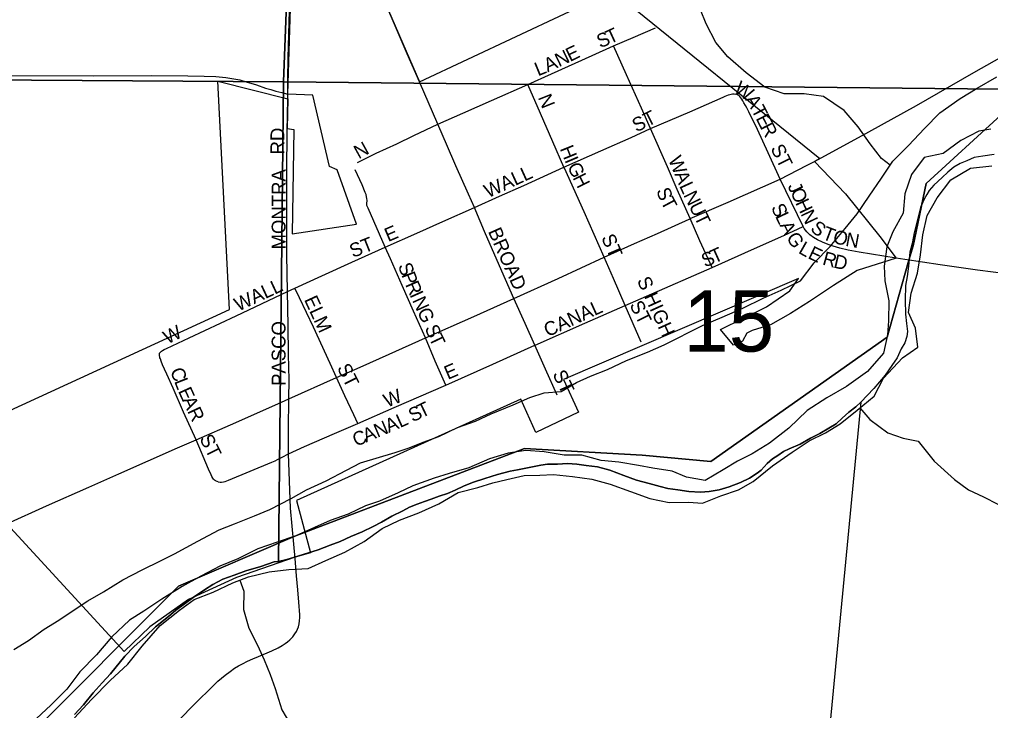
# Model space of a CAD drawing. Extents: x 0 to 1391, y -24 to 440.
# Drawn here: x 599.74 to 613.03, y 326.06 to 335.51 of the extents above; entities that cross this region are included whole.
import ezdxf

# ---------------------------------------------------------------- set-up
doc = ezdxf.new("R2010")
doc.units = 0
for name, color, linetype in [('GM_X_City_Street', 7, 'Continuous'), ('GM_X_City_Street_Text', 7, 'Continuous'), ('GM_X_Corporation', 7, 'Continuous'), ('GM_X_County_Road', 7, 'Continuous'), ('GM_X_Major_River', 7, 'Continuous'), ('GM_X_Minor_River', 7, 'Continuous'), ('GM_X_Section', 7, 'Continuous'), ('GM_X_Section_Text', 7, 'Continuous'), ('GM_X_State_Route', 7, 'Continuous'), ('GM_X_Township', 7, 'Continuous'), ('GM_X_Township_Road', 7, 'Continuous')]:
    doc.layers.add(name, color=color, linetype=linetype)

msp = doc.modelspace()

# ---------------------------------------------------------------- linework, layer by layer
at = {"layer": 'GM_X_City_Street'}
for points in [[(607.874, 335.147), (608.14, 335.263), (608.447, 335.393)], [(606.7, 334.62), (607.024, 334.766), (607.578, 335.015), (607.874, 335.147)], [(608.378, 334.016), (608.253, 334.296), (608.052, 334.75), (607.874, 335.147)], [(605.469, 334.077), (605.218, 334.654)], [(605.469, 334.077), (605.809, 334.228), (606.202, 334.4), (606.7, 334.62)], [(607.193, 333.49), (607.041, 333.835), (606.872, 334.223), (606.7, 334.62)], [(608.378, 334.016), (608.916, 334.247), (609.372, 334.448), (609.402, 334.46), (609.424, 334.469), (609.445, 334.477), (609.466, 334.483), (609.483, 334.488), (609.502, 334.491), (609.522, 334.492), (609.54, 334.488)], [(610.153, 333.326), (609.99, 333.683), (609.841, 334.002), (609.723, 334.246), (609.696, 334.299), (609.678, 334.33), (609.656, 334.37), (609.642, 334.396), (609.628, 334.419), (609.615, 334.437), (609.602, 334.455), (609.59, 334.466), (609.577, 334.474), (609.559, 334.483), (609.54, 334.488)], [(604.368, 333.554), (604.625, 333.679), (604.905, 333.809), (605.14, 333.921), (605.469, 334.077)], [(605.968, 332.939), (605.887, 333.121), (605.716, 333.506), (605.588, 333.802), (605.483, 334.045), (605.469, 334.077)], [(607.193, 333.49), (607.699, 333.714), (608.112, 333.895), (608.378, 334.016)], [(608.922, 332.785), (608.745, 333.183), (608.611, 333.491), (608.378, 334.016)], [(603.401, 332.556), (603.4, 332.631), (603.402, 333.047), (603.399, 333.426), (603.406, 333.978)], [(605.968, 332.939), (606.314, 333.09), (606.647, 333.24), (607.193, 333.49)], [(607.746, 332.259), (607.471, 332.88), (607.201, 333.473), (607.193, 333.49)], [(604.747, 332.395), (604.513, 332.927), (604.506, 332.944), (604.501, 332.955), (604.497, 332.965), (604.495, 332.974), (604.495, 332.987), (604.496, 332.996), (604.498, 333.008), (604.499, 333.019), (604.5, 333.034), (604.498, 333.06), (604.493, 333.084), (604.485, 333.114), (604.474, 333.143), (604.43, 333.246), (604.337, 333.451)], [(610.468, 332.675), (610.153, 333.326)], [(604.747, 332.395), (605.179, 332.585), (605.534, 332.744), (605.968, 332.939)], [(606.508, 331.692), (606.282, 332.211), (606.105, 332.608), (605.988, 332.892), (605.968, 332.939)], [(609.221, 332.117), (609.055, 332.481), (608.922, 332.785)], [(603.412, 331.787), (603.402, 332.292), (603.401, 332.556)], [(609.221, 332.117), (609.803, 332.377), (610.201, 332.553), (610.468, 332.675)], [(611.74, 332.246), (611.234, 332.326), (611.083, 332.355), (610.971, 332.379), (610.878, 332.406), (610.811, 332.431), (610.734, 332.463), (610.665, 332.495), (610.607, 332.529), (610.559, 332.564), (610.516, 332.605), (610.48, 332.651), (610.468, 332.675)], [(603.51, 331.832), (603.881, 332.004), (604.29, 332.189), (604.747, 332.395)], [(605.298, 331.154), (605.136, 331.518), (604.979, 331.87), (604.818, 332.234), (604.747, 332.395)], [(608.031, 331.598), (607.872, 331.967), (607.746, 332.259)], [(608.031, 331.598), (608.325, 331.723), (609.221, 332.117)], [(601.66, 330.943), (601.667, 330.954), (601.676, 330.965), (601.687, 330.973), (601.699, 330.98), (601.724, 330.993), (601.755, 331.009), (602.063, 331.156), (602.706, 331.454), (603.412, 331.787)], [(603.412, 331.787), (603.51, 331.832)], [(603.428, 330.32), (603.431, 330.582), (603.426, 330.927), (603.419, 331.322), (603.412, 331.787)], [(604.083, 330.613), (603.995, 330.803), (603.765, 331.3), (603.575, 331.7), (603.51, 331.832)], [(606.797, 331.053), (606.663, 331.352), (606.508, 331.692)], [(606.797, 331.053), (606.8, 331.055), (607.481, 331.357), (608.031, 331.598)], [(608.249, 331.097), (608.031, 331.598)], [(605.575, 330.507), (605.431, 330.835), (605.298, 331.154)], [(605.575, 330.507), (606.222, 330.793), (606.797, 331.053)], [(607.101, 330.372), (606.942, 330.724), (606.797, 331.053)], [(602.161, 329.76), (601.988, 330.138), (601.845, 330.465), (601.758, 330.656), (601.728, 330.724), (601.701, 330.786), (601.683, 330.834), (601.67, 330.868), (601.665, 330.88), (601.661, 330.893), (601.658, 330.905), (601.657, 330.917), (601.657, 330.931), (601.66, 330.943)], [(604.371, 329.985), (604.317, 330.1), (604.196, 330.361), (604.083, 330.613)], [(604.371, 329.985), (604.869, 330.204), (605.575, 330.507)], [(603.422, 329.568), (603.422, 329.911), (603.428, 330.32)], [(603.422, 329.568), (603.642, 329.668), (604.055, 329.847), (604.371, 329.985)], [(602.463, 329.185), (602.447, 329.189), (602.424, 329.198), (602.409, 329.21), (602.396, 329.223), (602.387, 329.237), (602.376, 329.258), (602.365, 329.281), (602.331, 329.36), (602.161, 329.76)], [(602.463, 329.185), (602.487, 329.182), (602.507, 329.182), (602.535, 329.187), (602.556, 329.192), (602.58, 329.2), (602.602, 329.209), (603.198, 329.455), (603.241, 329.474), (603.275, 329.491), (603.31, 329.507), (603.336, 329.522), (603.422, 329.568)], [(603.514, 328.138), (603.497, 328.332), (603.453, 328.827), (603.422, 329.568)]]:
    msp.add_lwpolyline(points, dxfattribs=at)
at = {"layer": 'GM_X_Corporation'}
for points in [[(598.982, 329.873), (602.617, 331.542), (602.457, 334.665), (603.413, 334.422), (603.406, 334.018), (603.495, 334.003), (603.472, 332.576), (604.355, 332.708), (604.092, 333.454), (603.987, 333.499), (603.758, 334.475), (603.414, 334.487), (603.529, 338.162)], [(604.656, 335.952), (605.218, 334.654), (607.865, 335.9), (610.698, 333.607), (610.621, 333.565), (611.049, 333.125), (611.515, 332.54), (611.74, 332.246), (611.209, 332.074), (610.882, 331.872), (610.555, 331.653), (610.294, 331.489), (610.019, 331.333), (609.772, 331.253), (609.699, 331.218), (609.637, 331.107), (609.515, 331.055), (609.336, 331.269), (609.964, 331.58), (610.287, 331.799), (610.405, 331.966), (607.189, 330.583), (607.391, 330.136), (606.809, 329.861), (606.602, 330.317), (603.535, 328.928), (603.723, 328.216), (603.513, 328.156), (602.712, 327.878), (602.056, 327.578), (601.527, 327.202), (601.176, 326.864), (599.57, 328.613)]]:
    msp.add_lwpolyline(points, dxfattribs=at)
at = {"layer": 'GM_X_County_Road'}
for points in [[(603.417, 334.687), (603.421, 334.983), (603.439, 335.628), (603.456, 336.049), (603.472, 336.506), (603.489, 336.95), (603.495, 337.173), (603.502, 337.384), (603.514, 337.77), (603.529, 338.162)], [(603.414, 334.487), (603.417, 334.687)], [(603.406, 333.978), (603.413, 334.422), (603.414, 334.487)], [(613.496, 331.997), (612.855, 332.081), (612.345, 332.153), (611.857, 332.226), (611.74, 332.246)], [(601.813, 325.809), (602.076, 326.087), (602.459, 326.459), (602.555, 326.54), (602.625, 326.593), (602.687, 326.635), (602.741, 326.667), (602.795, 326.695), (602.863, 326.732), (602.938, 326.765), (603.012, 326.798), (603.195, 326.874), (603.283, 326.916), (603.336, 326.946), (603.379, 326.975), (603.412, 326.998), (603.443, 327.023), (603.483, 327.064), (603.512, 327.107), (603.534, 327.138), (603.549, 327.168), (603.56, 327.204), (603.57, 327.243), (603.576, 327.286), (603.58, 327.329), (603.58, 327.367), (603.566, 327.538), (603.552, 327.707), (603.535, 327.898), (603.514, 328.138)]]:
    msp.add_lwpolyline(points, dxfattribs=at)
at = {"layer": 'GM_X_Major_River'}
for points in [[(613.034, 334.007), (612.871, 333.982), (612.625, 333.852), (612.384, 333.675)], [(612.384, 333.675), (612.124, 333.621), (611.951, 333.389), (611.86, 333.125), (611.838, 332.859), (611.695, 332.604), (611.614, 332.4), (611.577, 332.135), (611.587, 331.936), (611.641, 331.661), (611.634, 331.387), (611.621, 331.197), (611.569, 330.947), (611.35, 330.694), (611.063, 330.488), (610.793, 330.335), (610.522, 330.159), (610.272, 329.921), (610.009, 329.715), (609.769, 329.569), (609.569, 329.467), (609.375, 329.35), (609.128, 329.204), (608.871, 329.249), (608.675, 329.33), (608.41, 329.374), (608.213, 329.41), (607.947, 329.455), (607.704, 329.476), (607.44, 329.551), (607.196, 329.55), (606.924, 329.595), (606.673, 329.616), (606.429, 329.577), (606.175, 329.499), (605.891, 329.377), (605.623, 329.3), (605.416, 329.237), (605.124, 329.13), (604.923, 329.036), (604.669, 328.921), (604.478, 328.857), (604.239, 328.741), (603.993, 328.656), (603.778, 328.562), (603.524, 328.447), (603.27, 328.362), (603.002, 328.27), (602.732, 328.132), (602.486, 328.031), (602.224, 327.893), (601.969, 327.755), (601.691, 327.579), (601.443, 327.418), (601.25, 327.294), (601.008, 327.064), (600.796, 326.818), (600.57, 326.587), (600.389, 326.348), (600.17, 326.133), (599.913, 325.888)], [(600.493, 325.957), (600.728, 326.21), (600.985, 326.47), (601.227, 326.693), (601.423, 326.939), (601.666, 327.222), (601.93, 327.429), (602.132, 327.576), (602.393, 327.676), (602.663, 327.806), (602.878, 327.885), (603.161, 327.954), (603.428, 327.985), (603.695, 328.001), (603.934, 328.109), (604.195, 328.224), (604.458, 328.37), (604.706, 328.547), (604.944, 328.662), (605.206, 328.762), (605.483, 328.885), (605.745, 329.038), (606.013, 329.107), (606.22, 329.171), (606.412, 329.219), (606.649, 329.274), (606.862, 329.276), (607.053, 329.287), (607.311, 329.257), (607.576, 329.22), (607.826, 329.153), (608.105, 329.055), (608.369, 328.957), (608.634, 328.904), (608.9, 328.905), (609.09, 328.893), (609.343, 328.993), (609.582, 329.078), (609.782, 329.188), (610.046, 329.402), (610.317, 329.593), (610.55, 329.747), (610.773, 329.856), (610.974, 329.98), (611.207, 330.164), (611.44, 330.356), (611.568, 330.604), (611.826, 330.88), (612.035, 331.027), (612.004, 331.286), (611.911, 331.502), (611.948, 331.767), (612.031, 332.039), (612.075, 332.29), (612.105, 332.563), (612.165, 332.828), (612.3, 333.068), (612.489, 333.314), (612.76, 333.475), (613.05, 333.506)]]:
    msp.add_lwpolyline(points, dxfattribs=at)
at = {"layer": 'GM_X_Minor_River'}
for points in [[(611.659, 333.514), (611.538, 333.605), (611.383, 333.807), (611.222, 334.039), (611.029, 334.265), (610.745, 334.455), (610.48, 334.492), (610.206, 334.491), (609.942, 334.581), (609.688, 334.778), (609.435, 334.998), (609.272, 335.192), (609.142, 335.447), (609.063, 335.639)], [(606.921, 330.402), (607.158, 330.419), (607.366, 330.543), (607.559, 330.629), (607.789, 330.723), (608.051, 330.845), (608.336, 330.96), (608.566, 331.061), (609.09, 331.322), (609.36, 331.437), (609.644, 331.559), (609.922, 331.697), (610.168, 331.805), (610.43, 331.935), (610.619, 332.182), (610.838, 332.404), (611.042, 332.651), (611.207, 332.852), (611.373, 333.091), (611.539, 333.338), (611.697, 333.57), (611.908, 333.786), (612.127, 334.016), (612.337, 334.232), (612.616, 334.43), (612.848, 334.569), (613.119, 334.722)], [(599.664, 326.892), (599.865, 327.016), (600.082, 327.171), (600.283, 327.295), (600.477, 327.427), (600.678, 327.559), (600.894, 327.683), (601.157, 327.844), (601.419, 327.982), (601.673, 328.105), (601.866, 328.199), (602.182, 328.374), (602.475, 328.527), (602.683, 328.613), (602.96, 328.72), (603.167, 328.806), (603.46, 328.959), (603.669, 329.075), (603.938, 329.198), (604.216, 329.343), (604.409, 329.445), (604.884, 329.585), (605.076, 329.649), (605.268, 329.728), (605.483, 329.806), (605.737, 329.929), (605.983, 330.014), (606.199, 330.115), (606.499, 330.237), (606.729, 330.338), (606.921, 330.402)], [(611.244, 330.195), (611.379, 330.038), (611.625, 329.857), (611.837, 329.783), (612.041, 329.74), (612.262, 329.468), (612.538, 329.217), (612.732, 329.075), (612.935, 328.979), (613.13, 328.882)], [(602.757, 327.84), (602.812, 327.688), (602.806, 327.437), (602.883, 327.184), (602.999, 326.952), (603.093, 326.752), (603.171, 326.552), (603.243, 326.36), (603.334, 326.068), (603.451, 325.867)]]:
    msp.add_lwpolyline(points, dxfattribs=at)
at = {"layer": 'GM_X_Section'}
for points in [[(603.709, 343.811), (603.356, 334.656), (583.361, 334.79), (583.446, 343.811)], [(618.064, 334.507), (603.356, 334.656), (603.709, 343.811)], [(583.361, 334.79), (603.356, 334.656), (603.288, 328.097), (603.227, 328.091), (603.044, 328.026), (602.839, 327.969), (602.679, 327.911), (602.526, 327.853), (602.388, 327.779), (602.274, 327.706), (602.12, 327.602), (601.998, 327.514), (601.883, 327.432), (601.782, 327.343), (601.606, 327.202), (601.467, 327.068), (601.313, 326.935), (601.182, 326.801), (600.989, 326.561), (600.873, 326.435), (600.749, 326.3), (600.618, 326.136), (600.494, 326.002)], [(613.08, 333.661), (612.928, 333.641), (612.807, 333.621), (612.707, 333.577), (612.616, 333.541), (612.532, 333.489), (612.447, 333.422), (612.37, 333.348), (612.255, 333.244), (612.193, 333.169), (612.162, 333.117), (612.122, 333.049), (612.075, 332.937), (612.034, 332.771), (611.986, 332.59), (611.96, 332.446), (611.928, 332.325), (611.91, 332.136), (611.892, 331.993), (611.867, 331.872), (611.864, 331.668), (611.868, 331.478), (611.881, 331.349), (611.894, 331.243), (611.885, 331.175), (611.861, 331.084), (611.807, 331.002), (611.752, 330.882), (611.682, 330.777), (611.588, 330.642), (611.434, 330.463), (611.256, 330.277), (611.187, 330.21), (611.095, 330.136), (611.003, 330.054), (610.918, 329.98), (610.818, 329.921), (610.696, 329.847), (610.566, 329.781), (610.428, 329.7), (610.276, 329.635), (610.199, 329.598), (610.123, 329.547), (610.046, 329.502), (609.977, 329.436), (609.892, 329.346), (609.838, 329.302), (609.731, 329.235), (609.609, 329.177), (609.456, 329.119), (609.319, 329.076), (609.182, 329.055), (609.061, 329.042), (608.902, 329.053), (608.751, 329.078), (608.615, 329.096), (608.509, 329.12), (608.359, 329.161), (608.185, 329.209), (608.012, 329.273), (607.824, 329.344), (607.651, 329.392), (607.499, 329.41), (607.371, 329.428), (607.242, 329.437), (607.106, 329.425), (606.97, 329.427), (606.878, 329.413), (606.559, 329.351), (606.46, 329.33), (606.369, 329.309), (606.285, 329.287), (606.11, 329.23), (605.958, 329.179), (605.828, 329.129), (605.706, 329.07), (605.599, 329.027), (605.485, 328.991), (605.378, 328.947), (605.287, 328.918), (605.187, 328.882), (605.081, 328.839), (604.989, 328.787), (604.836, 328.714), (604.698, 328.633), (604.584, 328.575), (604.431, 328.501), (604.278, 328.436), (604.133, 328.37), (603.996, 328.32), (603.828, 328.254), (603.554, 328.168), (603.402, 328.125), (603.288, 328.097), (603.356, 334.656), (618.064, 334.507)], [(613.08, 333.661), (612.928, 333.641), (612.807, 333.621), (612.707, 333.577), (612.616, 333.541), (612.532, 333.489), (612.447, 333.422), (612.37, 333.348), (612.255, 333.244), (612.193, 333.169), (612.162, 333.117), (612.122, 333.049), (612.075, 332.937), (612.034, 332.771), (611.986, 332.59), (611.96, 332.446), (611.928, 332.325), (611.91, 332.136), (611.892, 331.993), (611.867, 331.872), (611.864, 331.668), (611.868, 331.478), (611.881, 331.349), (611.894, 331.243), (611.885, 331.175), (611.861, 331.084), (611.807, 331.002), (611.752, 330.882), (611.682, 330.777), (611.588, 330.642), (611.434, 330.463), (611.256, 330.277), (610.008, 317.239)], [(600.494, 326.002), (600.618, 326.136), (600.749, 326.3), (600.873, 326.435), (600.989, 326.561), (601.182, 326.801), (601.313, 326.935), (601.467, 327.068), (601.606, 327.202), (601.782, 327.343), (601.883, 327.432), (601.998, 327.514), (602.12, 327.602), (602.274, 327.706), (602.388, 327.779), (602.526, 327.853), (602.679, 327.911), (602.839, 327.969), (603.044, 328.026), (603.227, 328.091), (603.288, 328.097), (603.402, 328.125), (603.554, 328.168), (603.828, 328.254), (603.996, 328.32), (604.133, 328.37), (604.278, 328.436), (604.431, 328.501), (604.584, 328.575), (604.698, 328.633), (604.836, 328.714), (604.989, 328.787), (605.081, 328.839), (605.187, 328.882), (605.287, 328.918), (605.378, 328.947), (605.485, 328.991), (605.599, 329.027), (605.706, 329.07), (605.828, 329.129), (605.958, 329.179), (606.11, 329.23), (606.285, 329.287), (606.369, 329.309), (606.46, 329.33), (606.559, 329.351), (606.878, 329.413), (606.97, 329.427), (607.106, 329.425), (607.242, 329.437), (607.371, 329.428), (607.499, 329.41), (607.651, 329.392), (607.824, 329.344), (608.012, 329.273), (608.185, 329.209), (608.359, 329.161), (608.509, 329.12), (608.615, 329.096), (608.751, 329.078), (608.902, 329.053), (609.061, 329.042), (609.182, 329.055), (609.319, 329.076), (609.456, 329.119), (609.609, 329.177), (609.731, 329.235), (609.838, 329.302), (609.892, 329.346), (609.977, 329.436), (610.046, 329.502), (610.123, 329.547), (610.199, 329.598), (610.276, 329.635), (610.428, 329.7), (610.566, 329.781), (610.696, 329.847), (610.818, 329.921), (610.918, 329.98), (611.003, 330.054), (611.095, 330.136), (611.187, 330.21), (611.256, 330.277), (610.008, 317.239)]]:
    msp.add_lwpolyline(points, dxfattribs=at)
at = {"layer": 'GM_X_State_Route'}
for points in [[(610.621, 333.565), (611.365, 333.972), (612.017, 334.334), (612.805, 334.784), (613.8, 335.346)], [(599.57, 328.613), (600.113, 328.855), (600.691, 329.114), (601.1, 329.294), (601.906, 329.649), (602.161, 329.76), (602.702, 329.998), (603.327, 330.275), (603.428, 330.32), (604.083, 330.613), (604.406, 330.755), (604.803, 330.933), (605.298, 331.154), (605.96, 331.447), (606.508, 331.692), (607.115, 331.966), (607.746, 332.259), (608.161, 332.444), (608.476, 332.581), (608.907, 332.778), (608.922, 332.785), (609.441, 333.008), (610.153, 333.326), (610.513, 333.51)], [(610.513, 333.51), (610.621, 333.565)]]:
    msp.add_lwpolyline(points, dxfattribs=at)
at = {"layer": 'GM_X_Township'}
for points in [[(613.178, 334.203), (612.15, 333.264), (611.972, 332.415), (611.907, 332.187), (611.616, 331.163), (609.203, 329.463), (608.264, 329.552), (606.654, 329.64), (603.509, 328.442), (601.917, 327.76), (595.664, 321.497), (594.905, 321.094), (594.279, 320.601), (593.744, 320.064), (592.001, 319.079), (591.778, 318.542), (590.711, 317.997), (589.749, 317.55), (588.873, 316.833), (587.903, 316.211), (586.32, 315.295)], [(586.32, 315.295), (587.903, 316.211), (588.873, 316.833), (589.749, 317.55), (590.711, 317.997), (591.778, 318.542), (592.001, 319.079), (593.744, 320.064), (594.279, 320.601), (594.905, 321.094), (595.664, 321.497), (601.917, 327.76), (603.509, 328.442), (606.654, 329.64), (608.264, 329.552), (609.203, 329.463), (611.616, 331.163), (611.907, 332.187), (611.972, 332.415), (612.15, 333.264), (613.178, 334.203)]]:
    msp.add_lwpolyline(points, dxfattribs=at)
at = {"layer": 'GM_X_Township_Road'}
for points in [[(605.218, 334.654), (605.047, 335.039), (604.842, 335.518), (604.656, 335.952)], [(599.498, 334.743), (600.753, 334.74), (601.548, 334.743), (602.044, 334.737), (602.268, 334.733), (602.429, 334.727), (602.565, 334.715), (602.675, 334.698), (602.759, 334.681), (602.843, 334.658), (602.984, 334.613), (603.111, 334.571), (603.181, 334.549), (603.252, 334.529), (603.332, 334.508), (603.414, 334.487)]]:
    msp.add_lwpolyline(points, dxfattribs=at)

# ---------------------------------------------------------------- texts
at = {"layer": 'GM_X_City_Street_Text'}
for s, height, rotation, p in [('T', 0.189, 24.7956, (607.821, 335.168)), ('S', 0.189, 22.3088, (607.689, 335.113)), ('N', 0.189, 25.6182, (607.126, 334.854)), ('E', 0.189, 25.6511, (607.276, 334.926)), ('A', 0.189, 24.4602, (606.97, 334.784)), ('L', 0.189, 22.187, (606.839, 334.73)), ('W', 0.189, 325.1209, (609.507, 334.525)), ('N', 0.189, 291.7939, (606.835, 334.443)), ('A', 0.189, 300.3414, (609.67, 334.417)), ('T', 0.189, 297.4812, (609.753, 334.275)), ('ST', 0.1894, 26.565, (608.186, 333.962)), ('E', 0.189, 297.298, (609.814, 334.157)), ('RD', 0.1894, 90, (603.366, 333.663)), ('R', 0.189, 297.304, (609.875, 334.038)), ('N', 0.189, 29.0443, (604.385, 333.595)), ('H', 0.189, 291.9272, (607.135, 333.743)), ('ST', 0.1894, 296.5651, (610.017, 333.746)), ('I', 0.189, 292.9078, (607.199, 333.585)), ('W', 0.189, 292.66, (608.618, 333.594)), ('WALL', 0.1894, 24.5364, (606.155, 333.063)), ('G', 0.189, 295.6333, (607.235, 333.5)), ('MONTRA', 0.1894, 90, (603.383, 332.363)), ('H', 0.189, 296.5499, (607.309, 333.346)), ('A', 0.189, 292.8034, (608.702, 333.393)), ('L', 0.189, 294.5978, (608.769, 333.234)), ('J', 0.189, 295.236, (610.251, 333.228)), ('S', 0.189, 289.3855, (608.455, 333.172)), ('T', 0.189, 298.0147, (608.512, 333.018)), ('N', 0.189, 295.7492, (608.826, 333.109)), ('O', 0.189, 295.2658, (610.287, 333.153)), ('U', 0.189, 295.8347, (608.899, 332.958)), ('S', 0.189, 295.6853, (610.024, 332.938)), ('H', 0.189, 295.2453, (610.358, 333.002)), ('T', 0.189, 295.8075, (608.972, 332.808)), ('L', 0.189, 295.723, (610.081, 332.818)), ('N', 0.189, 295.2355, (610.429, 332.852)), ('E', 0.189, 23.1873, (604.788, 332.463)), ('A', 0.189, 296.434, (610.14, 332.695)), ('S', 0.189, 320.2207, (610.554, 332.63)), ('T', 0.189, 339.168, (610.716, 332.51)), ('BROAD', 0.1894, 293.9638, (606.151, 332.611)), ('ST', 0.1894, 293.2005, (607.701, 332.527)), ('G', 0.189, 304.2303, (610.229, 332.522)), ('O', 0.189, 346.4123, (610.865, 332.455)), ('N', 0.189, 349.296, (611.038, 332.414)), ('ST', 0.1894, 21.7989, (604.305, 332.246)), ('L', 0.189, 330.3734, (610.391, 332.321)), ('S', 0.189, 22.9582, (609.123, 332.114)), ('T', 0.189, 24.2256, (609.25, 332.167)), ('E', 0.189, 334.531, (610.521, 332.248)), ('R', 0.189, 344.5265, (610.721, 332.159)), ('D', 0.189, 346.9509, (610.874, 332.117)), ('S', 0.189, 290.6296, (604.919, 332.142)), ('P', 0.189, 291.13, (604.966, 332.016)), ('WALL', 0.1894, 25.0177, (602.737, 331.512)), ('R', 0.189, 293.509, (605.018, 331.884)), ('S HIGH', 0.1894, 294.3423, (608.189, 331.941)), ('I', 0.189, 294.2667, (605.079, 331.744)), ('ELM', 0.1894, 294.7762, (603.634, 331.678)), ('N', 0.189, 294.2941, (605.113, 331.668)), ('CANAL', 0.1894, 24.3603, (606.971, 331.163)), ('ST', 0.1894, 296.5651, (608.087, 331.606)), ('G', 0.189, 294.3092, (605.181, 331.516)), ('PASCO', 0.1894, 90, (603.383, 330.497)), ('W', 0.189, 26.565, (601.769, 331.062)), ('S', 0.189, 291.5985, (605.286, 331.292)), ('T', 0.189, 295.5954, (605.341, 331.155)), ('C', 0.189, 289.7943, (601.802, 330.709)), ('ST', 0.1894, 296.5651, (604.084, 330.746)), ('E', 0.189, 23.1873, (605.605, 330.579)), ('ST', 0.1894, 295.0177, (607.034, 330.662)), ('L', 0.189, 291.7714, (601.856, 330.561)), ('E', 0.189, 294.6374, (601.909, 330.427)), ('W', 0.189, 22.6081, (604.773, 330.197)), ('A', 0.189, 295.014, (601.965, 330.305)), ('T', 0.189, 25.5954, (605.243, 330.054)), ('R', 0.189, 295.0228, (602.036, 330.154)), ('S', 0.189, 25.2233, (605.121, 329.997)), ('N', 0.189, 22.9897, (604.64, 329.786)), ('A', 0.189, 23.6548, (604.796, 329.852)), ('L', 0.189, 24.2888, (604.951, 329.92)), ('A', 0.189, 22.8284, (604.486, 329.721)), ('ST', 0.1894, 296.5651, (602.201, 329.779)), ('C', 0.189, 22.8478, (604.348, 329.663))]:
    msp.add_text(s, height=height, rotation=rotation, dxfattribs=at).set_placement(p)
at = {"layer": 'GM_X_Section_Text'}
msp.add_text('15', height=0.8371, rotation=0, dxfattribs=at).set_placement((608.827, 330.967))

doc.saveas('drawing.dxf')
